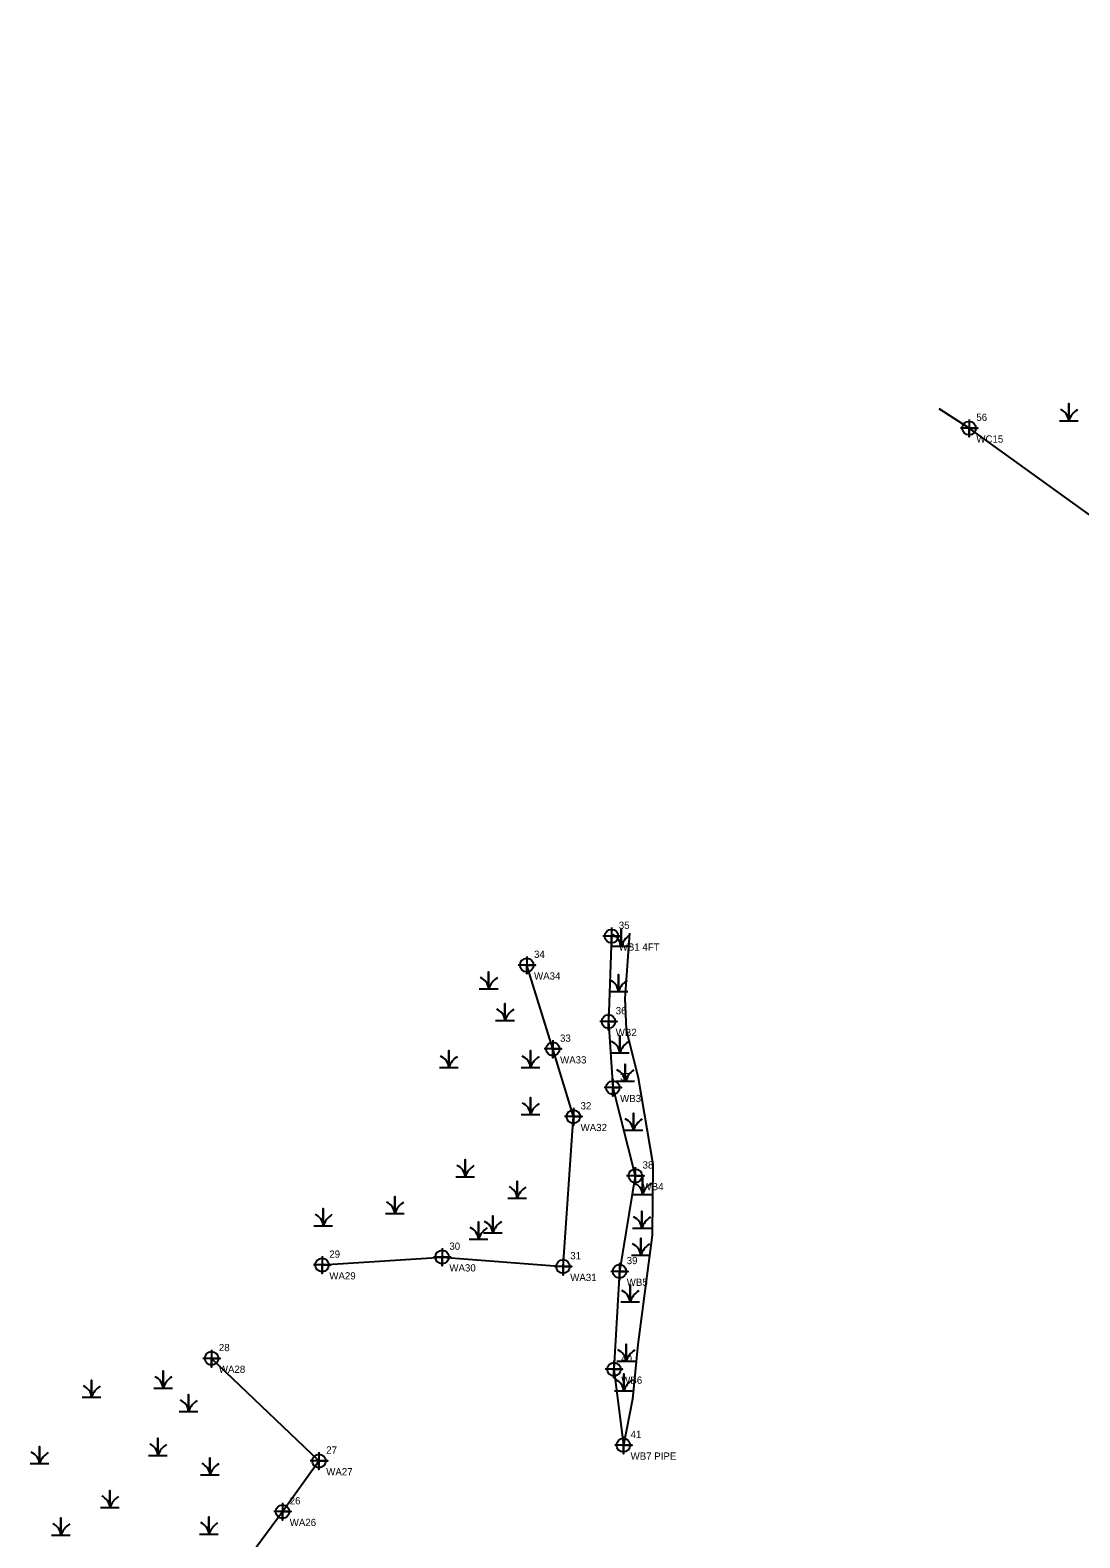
# Model space of a CAD drawing. Extents: x 2189822 to 2191198, y 387253 to 388663.
# Drawn here: x 2190230 to 2190593, y 388137 to 388658 of the extents above; entities that cross this region are included whole.
import ezdxf

# ---------------------------------------------------------------- set-up
doc = ezdxf.new("R2010")
doc.units = 0
for name, color, linetype in [('Structure020030_Alleghany', 7, 'Continuous'), ('Structure040008_Ashe', 7, 'Continuous'), ('Structure090007_Brunswick', 7, 'Continuous'), ('Structure620024_Moore', 7, 'Continuous'), ('Structure780124_Rockingham', 7, 'Continuous')]:
    doc.layers.add(name, color=color, linetype=linetype)

msp = doc.modelspace()

# ---------------------------------------------------------------- linework, layer by layer
at = {"layer": 'Structure020030_Alleghany'}
for points in [[(2190554.41, 388523.35), (2190554.41, 388517.35), (2190554.41, 388520.35), (2190557.41, 388520.35), (2190551.41, 388520.35)], [(2190430.93, 388347.81), (2190430.93, 388341.81), (2190430.93, 388344.81), (2190433.93, 388344.81), (2190427.93, 388344.81)], [(2190401.66, 388337.81), (2190401.66, 388331.81), (2190401.66, 388334.81), (2190404.66, 388334.81), (2190398.66, 388334.81)], [(2190429.88, 388318.3), (2190429.88, 388312.3), (2190429.88, 388315.3), (2190432.88, 388315.3), (2190426.88, 388315.3)], [(2190410.65, 388308.82), (2190410.65, 388302.82), (2190410.65, 388305.82), (2190413.65, 388305.82), (2190407.65, 388305.82)], [(2190431.38, 388295.47), (2190431.38, 388289.47), (2190431.38, 388292.47), (2190434.38, 388292.47), (2190428.38, 388292.47)], [(2190417.74, 388285.44), (2190417.74, 388279.44), (2190417.74, 388282.44), (2190420.74, 388282.44), (2190414.74, 388282.44)], [(2190439.14, 388265.01), (2190439.14, 388259.01), (2190439.14, 388262.01), (2190442.14, 388262.01), (2190436.14, 388262.01)], [(2190372.42, 388236.94), (2190372.42, 388230.94), (2190372.42, 388233.94), (2190375.42, 388233.94), (2190369.42, 388233.94)], [(2190330.96, 388234.19), (2190330.96, 388228.19), (2190330.96, 388231.19), (2190333.96, 388231.19), (2190327.96, 388231.19)], [(2190414.17, 388233.64), (2190414.17, 388227.64), (2190414.17, 388230.64), (2190417.17, 388230.64), (2190411.17, 388230.64)], [(2190433.67, 388231.97), (2190433.67, 388225.97), (2190433.67, 388228.97), (2190436.67, 388228.97), (2190430.67, 388228.97)], [(2190292.82, 388201.91), (2190292.82, 388195.91), (2190292.82, 388198.91), (2190295.82, 388198.91), (2190289.82, 388198.91)], [(2190431.77, 388198.14), (2190431.77, 388192.14), (2190431.77, 388195.14), (2190434.77, 388195.14), (2190428.77, 388195.14)], [(2190435.01, 388171.9), (2190435.01, 388165.9), (2190435.01, 388168.9), (2190438.01, 388168.9), (2190432.01, 388168.9)], [(2190329.9, 388166.48), (2190329.9, 388160.48), (2190329.9, 388163.48), (2190332.9, 388163.48), (2190326.9, 388163.48)], [(2190317.29, 388148.97), (2190317.29, 388142.97), (2190317.29, 388145.97), (2190320.29, 388145.97), (2190314.29, 388145.97)]]:
    msp.add_lwpolyline(points, dxfattribs=at)
for centre in [(2190554.41, 388520.35), (2190430.93, 388344.81), (2190401.66, 388334.81), (2190429.88, 388315.3), (2190410.65, 388305.82), (2190431.38, 388292.47), (2190417.74, 388282.44), (2190439.14, 388262.01), (2190372.42, 388233.94), (2190330.96, 388231.19), (2190414.17, 388230.64), (2190433.67, 388228.97), (2190292.82, 388198.91), (2190431.77, 388195.14), (2190435.01, 388168.9), (2190329.9, 388163.48), (2190317.29, 388145.97)]:
    msp.add_circle(centre, 2.34, dxfattribs=at)
at = {"layer": 'Structure620024_Moore'}
msp.add_line((2190554.41, 388520.35), (2190544.13, 388526.98), dxfattribs=at)
for points in [[(2190675.12, 388657.89), (2190732.67, 388650.96), (2190775.08, 388648.89), (2190808.98, 388656.55), (2190827.29, 388624.95), (2190799.88, 388590.51), (2190781.92, 388554.07), (2190732.61, 388504.35), (2190689.18, 388462.15), (2190644.41, 388421.14), (2190606.06, 388381.2), (2190596.27, 388413.53), (2190609.56, 388455.58), (2190598.83, 388488.32), (2190554.41, 388520.35)], [(2190430.93, 388344.81), (2190429.88, 388315.3), (2190431.38, 388292.47), (2190439.14, 388262.01), (2190433.67, 388228.97), (2190431.77, 388195.14), (2190435.01, 388168.9)], [(2190437.15, 388345.85), (2190435.54, 388323.27), (2190435.94, 388312.59), (2190440.18, 388295.86), (2190445.21, 388266.03), (2190445.01, 388241.43), (2190439.97, 388203.74), (2190438.16, 388184.79), (2190435.01, 388168.9)], [(2190330.96, 388231.19), (2190372.42, 388233.94), (2190414.17, 388230.64), (2190417.74, 388282.44), (2190410.65, 388305.82), (2190401.66, 388334.81)], [(2190303.02, 388126.66), (2190317.29, 388145.97), (2190329.9, 388163.48), (2190292.82, 388198.91)]]:
    msp.add_lwpolyline(points, dxfattribs=at)
at = {"layer": 'Structure780124_Rockingham'}
for p, q in [((2190588.8, 388525.58), (2190588.8, 388525.58)), ((2190434.21, 388343.98), (2190434.21, 388343.98)), ((2190388.49, 388329.25), (2190388.49, 388329.25)), ((2190433.29, 388328.32), (2190433.29, 388328.32)), ((2190394.13, 388318.32), (2190394.13, 388318.32)), ((2190433.75, 388307.12), (2190433.75, 388307.12)), ((2190374.74, 388302.09), (2190374.74, 388302.09)), ((2190402.95, 388302.09), (2190402.95, 388302.09)), ((2190435.59, 388297.33), (2190435.59, 388297.33)), ((2190402.95, 388285.86), (2190402.95, 388285.86)), ((2190438.47, 388280.4), (2190438.47, 388280.4)), ((2190380.38, 388264.35), (2190380.38, 388264.35)), ((2190398.36, 388256.94), (2190398.36, 388256.94)), ((2190441.64, 388258.26), (2190441.64, 388258.26)), ((2190356.06, 388251.65), (2190356.06, 388251.65)), ((2190331.38, 388247.41), (2190331.38, 388247.41)), ((2190441.35, 388246.54), (2190441.35, 388246.54)), ((2190384.97, 388242.83), (2190384.97, 388242.83)), ((2190389.9, 388244.95), (2190389.9, 388244.95)), ((2190441, 388237.21), (2190441, 388237.21)), ((2190437.32, 388221.08), (2190437.32, 388221.08)), ((2190435.94, 388200.58), (2190435.94, 388200.58)), ((2190276.04, 388191.33), (2190276.04, 388191.33)), ((2190435.13, 388190.33), (2190435.13, 388190.33)), ((2190251.36, 388188.15), (2190251.36, 388188.15)), ((2190284.85, 388183.21), (2190284.85, 388183.21)), ((2190274.27, 388168.05), (2190274.27, 388168.05)), ((2190233.38, 388165.22), (2190233.38, 388165.22)), ((2190292.25, 388161.34), (2190292.25, 388161.34)), ((2190257.7, 388150.06), (2190257.7, 388150.06)), ((2190240.78, 388140.53), (2190240.78, 388140.53)), ((2190291.9, 388140.88), (2190291.9, 388140.88))]:
    msp.add_line(p, q, dxfattribs=at)
for points in [[(2190585.58, 388522.9), (2190588.8, 388522.9), (2190588.8, 388528.82), (2190588.8, 388522.9), (2190592.03, 388522.9)], [(2190430.99, 388341.31), (2190434.21, 388341.31), (2190434.21, 388347.23), (2190434.21, 388341.31), (2190437.44, 388341.31)], [(2190385.27, 388326.58), (2190388.49, 388326.58), (2190388.49, 388332.5), (2190388.49, 388326.58), (2190391.72, 388326.58)], [(2190430.07, 388325.64), (2190433.29, 388325.64), (2190433.29, 388331.56), (2190433.29, 388325.64), (2190436.52, 388325.64)], [(2190390.91, 388315.64), (2190394.13, 388315.64), (2190394.13, 388321.56), (2190394.13, 388315.64), (2190397.36, 388315.64)], [(2190430.53, 388304.45), (2190433.75, 388304.45), (2190433.75, 388310.37), (2190433.75, 388304.45), (2190436.98, 388304.45)], [(2190371.52, 388299.42), (2190374.74, 388299.42), (2190374.74, 388305.33), (2190374.74, 388299.42), (2190377.97, 388299.42)], [(2190399.72, 388299.42), (2190402.95, 388299.42), (2190402.95, 388305.33), (2190402.95, 388299.42), (2190406.17, 388299.42)], [(2190432.37, 388294.66), (2190435.59, 388294.66), (2190435.59, 388300.58), (2190435.59, 388294.66), (2190438.82, 388294.66)], [(2190399.72, 388283.19), (2190402.95, 388283.19), (2190402.95, 388289.11), (2190402.95, 388283.19), (2190406.17, 388283.19)], [(2190435.25, 388277.73), (2190438.47, 388277.73), (2190438.47, 388283.64), (2190438.47, 388277.73), (2190441.7, 388277.73)], [(2190377.16, 388261.67), (2190380.38, 388261.67), (2190380.38, 388267.59), (2190380.38, 388261.67), (2190383.61, 388261.67)], [(2190438.42, 388255.59), (2190441.64, 388255.59), (2190441.64, 388261.5), (2190441.64, 388255.59), (2190444.87, 388255.59)], [(2190395.14, 388254.26), (2190398.36, 388254.26), (2190398.36, 388260.18), (2190398.36, 388254.26), (2190401.59, 388254.26)], [(2190352.83, 388248.97), (2190356.06, 388248.97), (2190356.06, 388254.89), (2190356.06, 388248.97), (2190359.29, 388248.97)], [(2190328.16, 388244.74), (2190331.38, 388244.74), (2190331.38, 388250.66), (2190331.38, 388244.74), (2190334.61, 388244.74)], [(2190381.74, 388240.15), (2190384.97, 388240.15), (2190384.97, 388246.07), (2190384.97, 388240.15), (2190388.19, 388240.15)], [(2190386.68, 388242.27), (2190389.9, 388242.27), (2190389.9, 388248.19), (2190389.9, 388242.27), (2190393.13, 388242.27)], [(2190438.12, 388243.86), (2190441.35, 388243.86), (2190441.35, 388249.78), (2190441.35, 388243.86), (2190444.58, 388243.86)], [(2190437.78, 388234.53), (2190441, 388234.53), (2190441, 388240.45), (2190441, 388234.53), (2190444.23, 388234.53)], [(2190434.1, 388218.41), (2190437.32, 388218.41), (2190437.32, 388224.32), (2190437.32, 388218.41), (2190440.55, 388218.41)], [(2190432.71, 388197.9), (2190435.94, 388197.9), (2190435.94, 388203.82), (2190435.94, 388197.9), (2190439.16, 388197.9)], [(2190272.81, 388188.65), (2190276.04, 388188.65), (2190276.04, 388194.57), (2190276.04, 388188.65), (2190279.26, 388188.65)], [(2190248.13, 388185.48), (2190251.36, 388185.48), (2190251.36, 388191.4), (2190251.36, 388185.48), (2190254.59, 388185.48)], [(2190431.91, 388187.65), (2190435.13, 388187.65), (2190435.13, 388193.57), (2190435.13, 388187.65), (2190438.36, 388187.65)], [(2190281.62, 388180.54), (2190284.85, 388180.54), (2190284.85, 388186.46), (2190284.85, 388180.54), (2190288.08, 388180.54)], [(2190230.16, 388162.55), (2190233.38, 388162.55), (2190233.38, 388168.47), (2190233.38, 388162.55), (2190236.61, 388162.55)], [(2190271.05, 388165.37), (2190274.27, 388165.37), (2190274.27, 388171.29), (2190274.27, 388165.37), (2190277.5, 388165.37)], [(2190289.03, 388158.67), (2190292.25, 388158.67), (2190292.25, 388164.59), (2190292.25, 388158.67), (2190295.48, 388158.67)], [(2190254.48, 388147.38), (2190257.71, 388147.38), (2190257.71, 388153.3), (2190257.71, 388147.38), (2190260.93, 388147.38)], [(2190237.56, 388137.86), (2190240.78, 388137.86), (2190240.78, 388143.77), (2190240.78, 388137.86), (2190244.01, 388137.86)], [(2190288.67, 388138.21), (2190291.9, 388138.21), (2190291.9, 388144.13), (2190291.9, 388138.21), (2190295.13, 388138.21)]]:
    msp.add_lwpolyline(points, dxfattribs=at)
for centre, radius, start, end in [((2190584.2, 388522.57), 4.61, 4.1403, 67.535), ((2190595.64, 388520.63), 7.21, 122.1274, 161.6222), ((2190429.61, 388340.97), 4.61, 4.1403, 67.535), ((2190441.05, 388339.03), 7.21, 122.1274, 161.6222), ((2190383.89, 388326.25), 4.61, 4.1403, 67.535), ((2190395.33, 388324.31), 7.21, 122.1274, 161.6222), ((2190428.69, 388325.31), 4.61, 4.1403, 67.535), ((2190440.13, 388323.37), 7.21, 122.1274, 161.6222), ((2190389.53, 388315.31), 4.61, 4.1403, 67.535), ((2190400.97, 388313.37), 7.21, 122.1274, 161.6222), ((2190429.15, 388304.12), 4.61, 4.1403, 67.535), ((2190440.59, 388302.18), 7.21, 122.1274, 161.6222), ((2190370.14, 388299.08), 4.61, 4.1403, 67.535), ((2190381.58, 388297.14), 7.21, 122.1274, 161.6222), ((2190398.35, 388299.08), 4.61, 4.1403, 67.535), ((2190409.79, 388297.14), 7.21, 122.1274, 161.6222), ((2190430.99, 388294.33), 4.61, 4.1403, 67.535), ((2190442.43, 388292.39), 7.21, 122.1274, 161.6222), ((2190398.35, 388282.86), 4.61, 4.1403, 67.535), ((2190409.79, 388280.92), 7.21, 122.1274, 161.6222), ((2190433.87, 388277.39), 4.61, 4.1403, 67.535), ((2190445.31, 388275.45), 7.21, 122.1274, 161.6222), ((2190375.78, 388261.34), 4.61, 4.1403, 67.535), ((2190387.23, 388259.4), 7.21, 122.1274, 161.6222), ((2190393.76, 388253.93), 4.61, 4.1403, 67.535), ((2190405.2, 388251.99), 7.21, 122.1274, 161.6222), ((2190437.04, 388255.25), 4.61, 4.1403, 67.535), ((2190448.48, 388253.31), 7.21, 122.1274, 161.6222), ((2190351.46, 388248.64), 4.61, 4.1403, 67.535), ((2190362.9, 388246.7), 7.21, 122.1274, 161.6222), ((2190326.78, 388244.41), 4.61, 4.1403, 67.535), ((2190338.22, 388242.47), 7.21, 122.1274, 161.6222), ((2190385.3, 388241.94), 4.61, 4.1403, 67.535), ((2190396.74, 388240), 7.21, 122.1274, 161.6222), ((2190436.75, 388243.53), 4.61, 4.1403, 67.535), ((2190448.19, 388241.59), 7.21, 122.1274, 161.6222), ((2190380.37, 388239.82), 4.61, 4.1403, 67.535), ((2190391.81, 388237.88), 7.21, 122.1274, 161.6222), ((2190436.4, 388234.2), 4.61, 4.1403, 67.535), ((2190447.85, 388232.26), 7.21, 122.1274, 161.6222), ((2190432.72, 388218.07), 4.61, 4.1403, 67.535), ((2190444.16, 388216.13), 7.21, 122.1274, 161.6222), ((2190431.34, 388197.57), 4.61, 4.1403, 67.535), ((2190442.78, 388195.63), 7.21, 122.1274, 161.6222), ((2190246.76, 388185.14), 4.61, 4.1403, 67.535), ((2190258.2, 388183.21), 7.21, 122.1274, 161.6222), ((2190271.44, 388188.32), 4.61, 4.1403, 67.535), ((2190282.88, 388186.38), 7.21, 122.1274, 161.6222), ((2190430.53, 388187.32), 4.61, 4.1403, 67.535), ((2190441.97, 388185.38), 7.21, 122.1274, 161.6222), ((2190280.25, 388180.21), 4.61, 4.1403, 67.535), ((2190291.69, 388178.27), 7.21, 122.1274, 161.6222), ((2190269.67, 388165.04), 4.61, 4.1403, 67.535), ((2190281.12, 388163.1), 7.21, 122.1274, 161.6222), ((2190228.78, 388162.22), 4.61, 4.1403, 67.535), ((2190240.22, 388160.28), 7.21, 122.1274, 161.6222), ((2190287.65, 388158.34), 4.61, 4.1403, 67.535), ((2190299.09, 388156.4), 7.21, 122.1274, 161.6222), ((2190253.11, 388147.05), 4.61, 4.1403, 67.535), ((2190264.55, 388145.11), 7.21, 122.1274, 161.6222), ((2190236.18, 388137.52), 4.61, 4.1403, 67.535), ((2190247.63, 388135.58), 7.21, 122.1274, 161.6222), ((2190287.3, 388137.88), 4.61, 4.1403, 67.535), ((2190298.74, 388135.94), 7.21, 122.1274, 161.6222)]:
    msp.add_arc(centre, radius, start, end, dxfattribs=at)

# ---------------------------------------------------------------- texts
at = {"layer": 'Structure040008_Ashe'}
for s, p in [('56', (2190556.91, 388522.85)), ('35', (2190433.43, 388347.31)), ('34', (2190404.16, 388337.31)), ('36', (2190432.38, 388317.8)), ('33', (2190413.15, 388308.32)), ('37', (2190433.88, 388294.97)), ('32', (2190420.24, 388284.94)), ('38', (2190441.64, 388264.51)), ('29', (2190333.46, 388233.69)), ('30', (2190374.92, 388236.44)), ('31', (2190416.67, 388233.14)), ('39', (2190436.17, 388231.47)), ('28', (2190295.32, 388201.41)), ('40', (2190434.27, 388197.64)), ('41', (2190437.51, 388171.4)), ('27', (2190332.4, 388165.98)), ('26', (2190319.79, 388148.47))]:
    msp.add_text(s, height=2.5, dxfattribs=at).set_placement(p)
at = {"layer": 'Structure090007_Brunswick'}
for s, p in [('WC15', (2190556.91, 388515.35)), ('WB1 4FT', (2190433.43, 388339.81)), ('WA34', (2190404.16, 388329.81)), ('WB2', (2190432.38, 388310.3)), ('WA33', (2190413.15, 388300.82)), ('WB3', (2190433.88, 388287.47)), ('WA32', (2190420.24, 388277.44)), ('WB4', (2190441.64, 388257.01)), ('WA30', (2190374.92, 388228.94)), ('WA29', (2190333.46, 388226.19)), ('WA31', (2190416.67, 388225.64)), ('WB5', (2190436.17, 388223.97)), ('WA28', (2190295.32, 388193.91)), ('WB6', (2190434.27, 388190.14)), ('WB7 PIPE', (2190437.51, 388163.9)), ('WA27', (2190332.4, 388158.48)), ('WA26', (2190319.79, 388140.97))]:
    msp.add_text(s, height=2.5, dxfattribs=at).set_placement(p)

doc.saveas('drawing.dxf')
